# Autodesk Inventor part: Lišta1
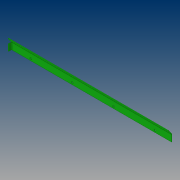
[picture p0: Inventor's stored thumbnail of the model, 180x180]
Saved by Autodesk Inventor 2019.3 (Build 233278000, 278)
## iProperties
Created: 2019-03
Part Number: Lišta1
Material: Ocel, legovaná
Document SubType Name: Plech
Designer: B-hon
Density: 7.73 g/cm^3
Sheet Metal Rule: Výchozí_mm
Appearance: Tmavě zelená
Author: B-hon
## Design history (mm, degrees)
node "Plocha1"
  sketch "Náčrt1"
    geometry: L1 (0, 0)-(716, 0); L2 (716, 0)-(716, 30); L3 (716, 30)-(0, 30); L4 (0, 30)-(0, 0)
    constraints: 8 end point, 2 parallel, 1 horizontal, 1 perpendicular
    dimensions: "d0" = 716 distance of L3.end L2.end; "d1" = 30 distance of L2.end L1.end
node "Obruba1"
node "Obruba2"
sketch "Náčrt4"
  geometry: L1 (0, 28.739)-(0, 0) reference; L2 (716, 0)-(4, 0) reference; 1 further point
  dimensions: "d23" = 642.5 distance from line of L1 point (642.5, 8); "d24" = 8 distance from line of L2 point (642.5, 8)
hole "Díra1" sketch "Náčrt4" at (642.5, 8) diameter "d25" = 5; stored, may be unused: countersink angle "d29" = 90 deg, drill point angle "d31" = 118 deg; dims "d26" = 6, "d27" = 8.7, "d28" = 2, "d30" = 2 (= Tloušťka)
pattern_linear "Obdélníkové pole1" dims "d34" = 185
node "Těleso1"
feature "Deska1" dims "d2" = 2 (= Tloušťka)
sketch "Náčrt2"
  geometry: L1 through (-358, 0) direction (1, 0); L2 through (0, 12.5) direction (0, 1); L3 (0, 25)-(-716, 25); L4 (-716, 25)-(-716, 0)
  constraints: 6 end point, 1 horizontal, 1 perpendicular, 1 vertical
feature "Deska2" dims "d2" = 2 (= Tloušťka), "d3" = 2 (= ŠířkaVýštipu), "d4" = 1 (= HloubkaVýštipu), "d5" = 4 (= MinimálníZbytek), "d6" = 2 (= PřechodovýPoloměr), "d7" = 25, "d8" = 35 deg, "d9" = 2 (= PoloměrOhybu), "d10" = 8 (= VelikostRohovéhoVýštipu), "d11" = 2 (= VelikostMezery), "d12" = 2 (= VelikostJacobihoPoloměru), "MezeraVystřižení" = 0.01
feature "Ohyb1" dims "d2" = 2 (= Tloušťka), "d3" = 2 (= ŠířkaVýštipu), "d4" = 1 (= HloubkaVýštipu), "d5" = 4 (= MinimálníZbytek), "d6" = 2 (= PřechodovýPoloměr), "d7" = 25, "d8" = 35 deg, "d9" = 2 (= PoloměrOhybu), "MezeraVystřižení" = 0.01
feature "Roh1" dims "d7" = 25, "d8" = 35 deg, "d10" = 8 (= VelikostRohovéhoVýštipu), "d11" = 2 (= VelikostMezery), "d12" = 2 (= VelikostJacobihoPoloměru)
sketch "Náčrt3"
  geometry: L1 through (-14.369, 0) direction (1, 0); L2 through (0, 7.5) direction (0, 1); L3 (0, 15)-(-28.739, 15); L4 (-28.739, 15)-(-28.739, 0)
  constraints: 6 end point, 1 horizontal, 1 perpendicular, 1 vertical
feature "Deska3" dims "d2" = 2 (= Tloušťka), "d13" = 2 (= ŠířkaVýštipu), "d14" = 1 (= HloubkaVýštipu), "d15" = 4 (= MinimálníZbytek), "d16" = 2 (= PřechodovýPoloměr), "d17" = 15, "d18" = 90 deg, "d19" = 2 (= PoloměrOhybu), "d20" = 8 (= VelikostRohovéhoVýštipu), "d21" = 2 (= VelikostMezery), "d22" = 2 (= VelikostJacobihoPoloměru), "MezeraVystřižení" = 0.01
feature "Ohyb2" dims "d2" = 2 (= Tloušťka), "d13" = 2 (= ŠířkaVýštipu), "d14" = 1 (= HloubkaVýštipu), "d15" = 4 (= MinimálníZbytek), "d16" = 2 (= PřechodovýPoloměr), "d17" = 15, "d18" = 90 deg, "d19" = 2 (= PoloměrOhybu), "MezeraVystřižení" = 0.01
feature "Roh2" dims "d17" = 15, "d18" = 90 deg, "d20" = 8 (= VelikostRohovéhoVýštipu), "d21" = 2 (= VelikostMezery), "d22" = 2 (= VelikostJacobihoPoloměru)
other parameters: "Tloušťka" = 2, "KSoučinitel" = 4.4, "PoloměrOhybu" = 2 (= Tloušťka), "ŠířkaVýštipu" = 2 (= Tloušťka), "HloubkaVýštipu" = 1 (= 0.5 x Tloušťka), "VelikostRohovéhoVýštipu" = 8 (= 4 x Tloušťka), "MinimálníZbytek" = 4 (= 2 x Tloušťka), "PřechodovýPoloměr" = 2 (= PoloměrOhybu), "VelikostJacobihoPoloměru" = 2 (= PoloměrOhybu), "VelikostMezery" = 2 (= Tloušťka)
